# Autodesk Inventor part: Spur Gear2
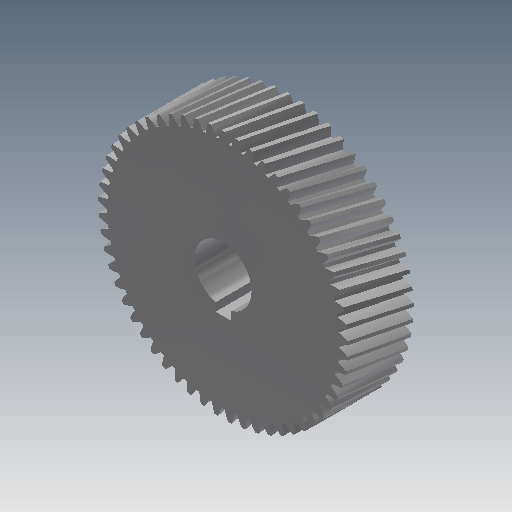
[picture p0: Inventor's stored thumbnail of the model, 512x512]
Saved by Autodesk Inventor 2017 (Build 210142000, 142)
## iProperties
Created: 2019-03
Part Number: Spur Gear2
Material: Steel
Document SubType Name: Modeling
Designer: user
Categories: <?xml version="1.0" encoding="UTF-16"?> <MemberInstance><Categories><FamilyTemplate><FamilyTemplateParameter ValueType="xs:double" Id="1" ObjectReferenceKey="da
Density: 7.85 g/cm^3
Appearance: Steel
Mass: 2107.77 g
Surface Area: 409.758 cm^2
Volume: 268.506 cm^3
CustomPartVersion: 1
Author: user
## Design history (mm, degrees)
sketch "Sketch1"
  geometry: C1 r 56.952 at (0, 0)
  constraints: 1 centre point
  dimensions: "d0" = 113.90425 diameter of C1 (= da_da)
extrude "Extrusion1" new body sketch "Sketch1" distance "d1" = 30 (= da_b); taper "d2" = 0 deg
workplane "Work Plane2"
sketch "Sketch2"
  geometry: C1 r 56.952 at (0, 0) reference; C2 r 56.337 at (0, 0)
  constraints: 1 centre point, 1 coincident
  dimensions: "d3" = 112.67442 diameter of C2 (= da_dw)
feature "Pitch Diameter" sketch "Sketch2" dims "d4" = 10, "d5" = 0
workplane "Work Plane8"
workplane "Work Plane9"
feature "Spur Gear" dims "d3" = 112.67442 (= da_dw), "da_b" = 30, "da_d" = 116.54683, "da_aw" = 85, "da_da" = 113.90425, "da_df" = 105.70541, "da_dw" = 112.67442, angle "da_beta" = 12 deg, "da_lefttooth" = 0, "da_righttooth" = 10
sketch "Sketch3"
  geometry: L1 (-3.483, -12.525)-(-3.483, -16.267); L2 (-3.483, -16.267)-(3.483, -16.267); L3 (3.483, -16.267)-(3.483, -12.525); A1 r 13 centre (0, 0) between (3.483, -12.525) and (-3.483, -12.525); 2 further points
  constraints: 6 end point, 2 point on circle, 1 centre point, 1 coincident, 1 midpoint, 1 parallel, 1 vertical alignment
  dimensions: "d49" = 26 diameter of A1
extrude "Extrusion2" cut sketch "Sketch3" stored distance "d50" = 10; taper "d51" = 0 deg
body "Solid1"
body "Srf1"
other parameters: "d16" = 85 (= da_aw), "d17" = 0, "d34" = 0.55116 (computed from da_z), "d39" = 0, "d41" = 0, "d43" = 85 (= da_aw), "d46" = 85 (= da_aw), "d47" = 0, "d48" = 0
